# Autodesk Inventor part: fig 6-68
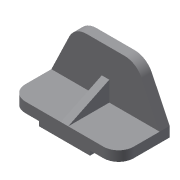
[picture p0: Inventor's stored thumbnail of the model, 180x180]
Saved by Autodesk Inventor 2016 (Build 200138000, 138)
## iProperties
Shininess: 77.0
Length Units: 11269
Angle Units: 11279
Time Units: 11290
Mass Units: 11283
Length Display Precision: 3
Angle Display Precision: 2
Created: 2001-12
Part Number: fig 6-68
Document SubType Name: Modeling
Designer: Renu Muthoo
Density: 1 g/cm^3
Material: Generic
Appearance: Default
Density: 0.0
Volumn: 0.0
Area: 0.0
PropertySet Name: Model Information
Control State: 0
Master: False
Checked Out: False
Author: Renu Muthoo
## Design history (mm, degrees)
node "Sketch1"
sketch "Sketch2"
  geometry: L1 (-67.219, 19.116)-(148.781, 19.116); L2 (148.781, 19.116)-(148.781, -0.884); L3 (-67.219, -0.884)-(-67.219, 19.116); L4 (-10.219, -0.884)-(-10.219, -9.884); L5 (-10.219, -9.884)-(91.781, -9.884); L6 (91.781, -9.884)-(91.781, -0.884); L7 (148.781, -0.884)-(91.781, -0.884); L8 (-10.219, -0.884)-(-67.219, -0.884)
  constraints: 16 end point, 5 parallel, 4 perpendicular, 2 equal length, 1 horizontal
  dimensions: "d0" = 102 distance of L4.end L5.end; "d1" = 57 distance of L4.start L3.start; "d2" = 29 distance between parallel lines of L1 L5; "d3" = 20 distance of L1.end L2.end
extrude "Extrusion1" new body sketch "Sketch2" distance "d4" = 102; taper "d5" = 0 deg
sketch "Sketch3"
  geometry: L1 (67.219, -19.116)-(-148.781, -19.116) reference; L2 (67.219, -19.116)-(31.475, -93.564); L3 (-2.781, -115.116)-(-78.781, -115.116); L4 (-113.038, -93.564)-(-148.781, -19.116); A1 r 38 centre (-2.781, -77.116) between (-2.781, -115.116) and (31.475, -93.564); A2 r 38 centre (-78.781, -77.116) between (-113.038, -93.564) and (-78.781, -115.116)
  constraints: 6 end point, 4 point on circle, 4 tangent, 2 centre point, 1 equal length, 1 equal radius, 1 parallel
  dimensions: "d6" = 96 distance between parallel lines of L3 L1; "d7" = 38 radius of A1; "d8" = 76 distance of A2.centre A1.centre
extrude "Extrusion2" join sketch "Sketch3" distance "d9" = 20; taper "d10" = 0 deg
fillet "Fillet1" dims "d11" = 30
workplane "Work Plane1"
sketch "Sketch7"
  geometry: L1 (0, -82)-(-39.557, 0)
  constraints: 2 end point
feature "Rib4" sketch "Sketch7" dims "d37" = 1, "d38" = 15, "d39" = 0
body "Solid1"
other parameters: "d12" = -108
